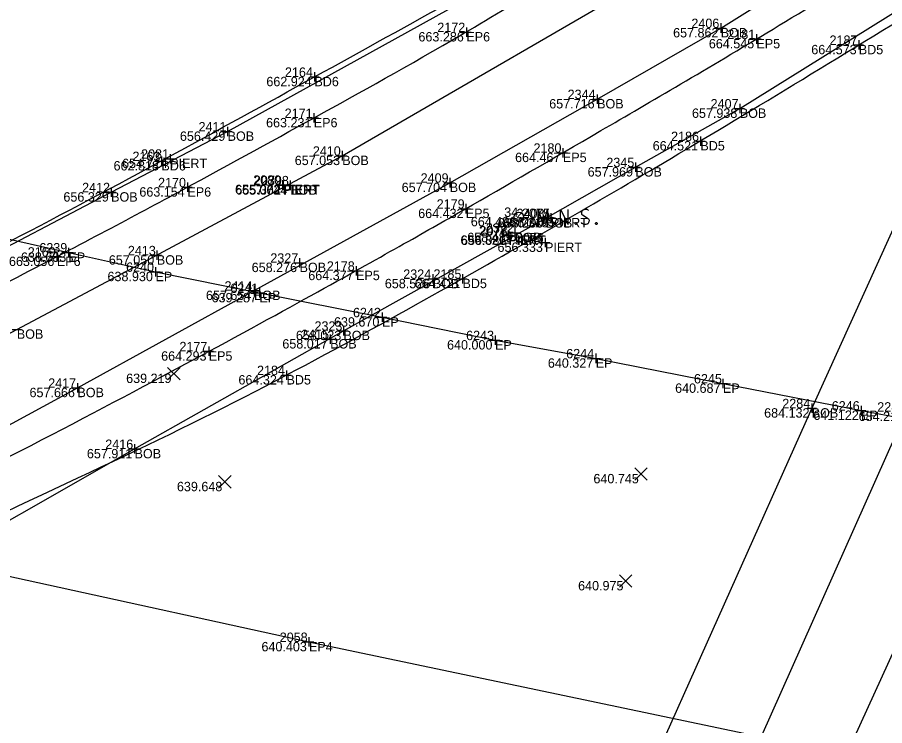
# Model space of a CAD drawing. Extents: x 2197382 to 2204062, y 634117 to 636522.
# Drawn here: x 2202538.2 to 2202630.7, y 635231.8 to 635307.3 of the extents above; entities that cross this region are included whole.
import ezdxf

# ---------------------------------------------------------------- set-up
doc = ezdxf.new("R2010")
doc.units = 0
for name, color, linetype in [('_CIVIL_CONSTRUCTION', 7, 'Continuous'), ('BR_X_SV_Bottom_of_Beam', 7, 'Continuous'), ('BR_X_SV_Bottom_of_Beam_Text', 7, 'Continuous'), ('BR_X_SV_Deck_Top', 7, 'Continuous'), ('BR_X_SV_Deck_Top_Text', 7, 'Continuous'), ('BR_X_SV_Pier_Cap_Top_Text', 7, 'Continuous'), ('GE_P_Alignment_100_Distances', 7, 'Continuous'), ('RW_X_CL_100_Curve_Data', 7, 'Continuous'), ('SH_Border', 7, 'Continuous'), ('SH_Cut_Line', 7, 'Continuous'), ('SH_Data', 7, 'Continuous'), ('SV_P_Control_Cells_Set', 7, 'Continuous')]:
    doc.layers.add(name, color=color, linetype=linetype)

msp = doc.modelspace()

# ---------------------------------------------------------------- linework, layer by layer
at = {"layer": '_CIVIL_CONSTRUCTION'}
for p, q in [((2202586.089, 635306.205), (2202586.089, 635305.205)), ((2202612.695, 635306.135), (2202613.695, 635306.135)), ((2202613.195, 635306.635), (2202613.195, 635305.635)), ((2202613.195, 635306.135), (2202613.195, 635306.135)), ((2202585.589, 635305.705), (2202586.589, 635305.705)), ((2202586.089, 635305.705), (2202586.089, 635305.705)), ((2202617, 635305.468), (2202617, 635304.468)), ((2202616.5, 635304.968), (2202617.5, 635304.968)), ((2202617, 635304.968), (2202617, 635304.968)), ((2202627.41, 635304.339), (2202628.41, 635304.339)), ((2202627.91, 635304.839), (2202627.91, 635303.839)), ((2202627.91, 635304.339), (2202627.91, 635304.339)), ((2202569.901, 635301.433), (2202569.901, 635300.433)), ((2202569.401, 635300.933), (2202570.401, 635300.933)), ((2202569.901, 635300.933), (2202569.901, 635300.933)), ((2202599.525, 635298.569), (2202600.525, 635298.569)), ((2202600.025, 635299.069), (2202600.025, 635298.069)), ((2202600.025, 635298.569), (2202600.025, 635298.569)), ((2202615.232, 635298.065), (2202615.232, 635297.065)), ((2202569.832, 635297.056), (2202569.832, 635296.056)), ((2202614.732, 635297.565), (2202615.732, 635297.565)), ((2202615.232, 635297.565), (2202615.232, 635297.565)), ((2202569.332, 635296.556), (2202570.332, 635296.556)), ((2202569.832, 635296.556), (2202569.832, 635296.556)), ((2202560.151, 635295.117), (2202561.151, 635295.117)), ((2202560.651, 635295.617), (2202560.651, 635294.617)), ((2202560.651, 635295.117), (2202560.651, 635295.117)), ((2202610.53, 635294.094), (2202611.53, 635294.094)), ((2202611.03, 635294.594), (2202611.03, 635293.594)), ((2202611.03, 635294.094), (2202611.03, 635294.094)), ((2202572.867, 635293.036), (2202572.867, 635292.036)), ((2202596.38, 635293.354), (2202596.38, 635292.354)), ((2202553.597, 635292.463), (2202553.597, 635291.463)), ((2202554.029, 635292.215), (2202555.029, 635292.215)), ((2202554.529, 635292.715), (2202554.529, 635291.715)), ((2202554.529, 635292.215), (2202554.529, 635292.215)), ((2202572.367, 635292.536), (2202573.367, 635292.536)), ((2202572.867, 635292.536), (2202572.867, 635292.536)), ((2202595.88, 635292.854), (2202596.88, 635292.854)), ((2202596.38, 635292.854), (2202596.38, 635292.854)), ((2202553.097, 635291.963), (2202554.097, 635291.963)), ((2202553.597, 635291.963), (2202553.597, 635291.963)), ((2202603.599, 635291.315), (2202604.599, 635291.315)), ((2202604.099, 635291.815), (2202604.099, 635290.815)), ((2202604.099, 635291.315), (2202604.099, 635291.315)), ((2202556.369, 635289.676), (2202556.369, 635288.676)), ((2202566.011, 635289.444), (2202567.011, 635289.444)), ((2202566.058, 635289.393), (2202567.058, 635289.393)), ((2202566.511, 635289.944), (2202566.511, 635288.944)), ((2202566.511, 635289.444), (2202566.511, 635289.444)), ((2202566.558, 635289.893), (2202566.558, 635288.893)), ((2202566.558, 635289.393), (2202566.558, 635289.393)), ((2202566.822, 635289.379), (2202567.822, 635289.379)), ((2202567.322, 635289.879), (2202567.322, 635288.879)), ((2202567.322, 635289.379), (2202567.322, 635289.379)), ((2202583.822, 635289.661), (2202584.822, 635289.661)), ((2202584.322, 635290.161), (2202584.322, 635289.161)), ((2202584.322, 635289.661), (2202584.322, 635289.661)), ((2202547.737, 635288.645), (2202548.737, 635288.645)), ((2202548.237, 635289.145), (2202548.237, 635288.145)), ((2202548.237, 635288.645), (2202548.237, 635288.645)), ((2202555.869, 635289.176), (2202556.869, 635289.176)), ((2202556.369, 635289.176), (2202556.369, 635289.176)), ((2202585.532, 635286.892), (2202586.532, 635286.892)), ((2202586.032, 635287.392), (2202586.032, 635286.392)), ((2202586.032, 635286.892), (2202586.032, 635286.892)), ((2202594.056, 635285.879), (2202595.056, 635285.879)), ((2202594.556, 635286.379), (2202594.556, 635285.379)), ((2202594.556, 635285.879), (2202594.556, 635285.879)), ((2202594.606, 635285.901), (2202595.606, 635285.901)), ((2202595.106, 635286.401), (2202595.106, 635285.401)), ((2202595.106, 635285.901), (2202595.106, 635285.901)), ((2202591.265, 635284.831), (2202591.265, 635283.831)), ((2202590.044, 635284.055), (2202591.044, 635284.055)), ((2202590.118, 635284.025), (2202591.118, 635284.025)), ((2202590.544, 635284.555), (2202590.544, 635283.555)), ((2202590.544, 635284.055), (2202590.544, 635284.055)), ((2202590.618, 635284.525), (2202590.618, 635283.525)), ((2202590.618, 635284.025), (2202590.618, 635284.025)), ((2202590.765, 635284.331), (2202591.765, 635284.331)), ((2202591.265, 635284.331), (2202591.265, 635284.331)), ((2202594.475, 635283.789), (2202594.475, 635282.789)), ((2202593.975, 635283.289), (2202594.975, 635283.289)), ((2202594.475, 635283.289), (2202594.475, 635283.289)), ((2202542.454, 635282.285), (2202542.454, 635281.285)), ((2202543.188, 635282.23), (2202544.188, 635282.23)), ((2202543.688, 635282.73), (2202543.688, 635281.73)), ((2202543.688, 635282.23), (2202543.688, 635282.23)), ((2202552.607, 635281.931), (2202553.607, 635281.931)), ((2202553.107, 635282.431), (2202553.107, 635281.431)), ((2202553.107, 635281.931), (2202553.107, 635281.931)), ((2202541.954, 635281.785), (2202542.954, 635281.785)), ((2202542.454, 635281.785), (2202542.454, 635281.785)), ((2202567.819, 635281.138), (2202568.819, 635281.138)), ((2202568.319, 635281.638), (2202568.319, 635280.638)), ((2202568.319, 635281.138), (2202568.319, 635281.138)), ((2202552.465, 635280.17), (2202553.465, 635280.17)), ((2202552.965, 635280.67), (2202552.965, 635279.67)), ((2202552.965, 635280.17), (2202552.965, 635280.17)), ((2202573.84, 635280.28), (2202574.84, 635280.28)), ((2202574.34, 635280.78), (2202574.34, 635279.78)), ((2202574.34, 635280.28), (2202574.34, 635280.28)), ((2202582.008, 635279.418), (2202583.008, 635279.418)), ((2202582.508, 635279.918), (2202582.508, 635278.918)), ((2202582.508, 635279.418), (2202582.508, 635279.418)), ((2202585.177, 635279.428), (2202586.177, 635279.428)), ((2202585.677, 635279.928), (2202585.677, 635278.928)), ((2202585.677, 635279.428), (2202585.677, 635279.428)), ((2202563.463, 635278.661), (2202563.463, 635277.661)), ((2202564.038, 635278.417), (2202564.038, 635277.417)), ((2202562.963, 635278.161), (2202563.963, 635278.161)), ((2202563.463, 635278.161), (2202563.463, 635278.161)), ((2202563.538, 635277.917), (2202564.538, 635277.917)), ((2202564.038, 635277.917), (2202564.038, 635277.917)), ((2202577.102, 635275.828), (2202577.102, 635274.828)), ((2202576.602, 635275.328), (2202577.602, 635275.328)), ((2202577.102, 635275.328), (2202577.102, 635275.328)), ((2202537.689, 635274.036), (2202538.689, 635274.036)), ((2202572.492, 635273.891), (2202573.492, 635273.891)), ((2202572.992, 635274.391), (2202572.992, 635273.391)), ((2202572.992, 635273.891), (2202572.992, 635273.891)), ((2202571.077, 635272.998), (2202572.077, 635272.998)), ((2202571.577, 635273.498), (2202571.577, 635272.498)), ((2202571.577, 635272.998), (2202571.577, 635272.998)), ((2202588.648, 635272.888), (2202589.648, 635272.888)), ((2202589.148, 635273.388), (2202589.148, 635272.388)), ((2202589.148, 635272.888), (2202589.148, 635272.888)), ((2202558.633, 635272.203), (2202558.633, 635271.203)), ((2202558.133, 635271.703), (2202559.133, 635271.703)), ((2202558.633, 635271.703), (2202558.633, 635271.703)), ((2202599.374, 635270.951), (2202600.374, 635270.951)), ((2202599.874, 635271.451), (2202599.874, 635270.451)), ((2202599.874, 635270.951), (2202599.874, 635270.951)), ((2202566.427, 635269.164), (2202567.427, 635269.164)), ((2202566.927, 635269.664), (2202566.927, 635268.664)), ((2202566.927, 635269.164), (2202566.927, 635269.164)), ((2202544.646, 635268.314), (2202544.646, 635267.314)), ((2202612.935, 635268.276), (2202613.935, 635268.276)), ((2202613.435, 635268.776), (2202613.435, 635267.776)), ((2202613.435, 635268.276), (2202613.435, 635268.276)), ((2202544.146, 635267.814), (2202545.146, 635267.814)), ((2202544.646, 635267.814), (2202544.646, 635267.814)), ((2202622.397, 635265.637), (2202623.397, 635265.637)), ((2202622.897, 635266.137), (2202622.897, 635265.137)), ((2202622.897, 635265.637), (2202622.897, 635265.637)), ((2202627.65, 635265.389), (2202628.65, 635265.389)), ((2202628.15, 635265.889), (2202628.15, 635264.889)), ((2202628.15, 635265.389), (2202628.15, 635265.389)), ((2202550.738, 635261.8), (2202550.738, 635260.8)), ((2202550.238, 635261.3), (2202551.238, 635261.3)), ((2202550.738, 635261.3), (2202550.738, 635261.3)), ((2202569.322, 635241.242), (2202569.322, 635240.242)), ((2202568.822, 635240.742), (2202569.822, 635240.742)), ((2202569.322, 635240.742), (2202569.322, 635240.742))]:
    msp.add_line(p, q, dxfattribs=at)
at = {"layer": 'BR_X_SV_Bottom_of_Beam'}
for points in [[(2202550.738, 635261.3), (2202572.992, 635273.891), (2202594.556, 635285.879), (2202604.099, 635291.315), (2202615.232, 635297.565), (2202632.636, 635308.407), (2202649.916, 635319.32), (2202686.545, 635342.9), (2202715.55, 635365.054), (2202734.551, 635379.543), (2202765.2, 635403.192), (2202782.887, 635418.269), (2202797.351, 635430.625), (2202810.639, 635442.162), (2202822.488, 635452.15)], [(2202513.324, 635270.745), (2202518.461, 635273.222), (2202532.26, 635280.283), (2202548.237, 635288.645), (2202560.651, 635295.117), (2202588.283, 635310.399), (2202608.693, 635322.992), (2202620.515, 635330.213), (2202626.072, 635333.707), (2202636.254, 635340.133), (2202656.933, 635353.888), (2202662.455, 635358.969), (2202720.902, 635399.769), (2202735.154, 635410.438), (2202760.7, 635432.077)], [(2202698.738, 635432.336), (2202647.005, 635318.77), (2202622.897, 635265.637), (2202604.224, 635223.888), (2202566.194, 635137.247)], [(2202700.297, 635413.559), (2202652.906, 635308.886), (2202632.96, 635265.277), (2202616.353, 635228.13), (2202571.256, 635128.111)], [(2202692.588, 635374.159), (2202661.746, 635305.712), (2202642.152, 635262.855), (2202627.428, 635230.558), (2202583.755, 635133.025)], [(2202600.025, 635298.569), (2202613.195, 635306.135), (2202629.349, 635316.236), (2202645.46, 635326.182), (2202658.228, 635335.017), (2202675.533, 635345.812), (2202692.151, 635358.452)], [(2202572.867, 635292.536), (2202609.773, 635313.94), (2202624.848, 635323.108)], [(2202480.61, 635236.776), (2202503.22, 635246.466), (2202521.809, 635255.415), (2202544.646, 635267.814), (2202563.463, 635278.161), (2202584.322, 635289.661), (2202600.025, 635298.569)], [(2202469.79, 635240.642), (2202482.107, 635245.978), (2202495.671, 635251.668), (2202517.657, 635263.17), (2202538.189, 635274.036), (2202552.84, 635281.789), (2202572.867, 635292.536)], [(2202495.198, 635233.737), (2202513.073, 635241.549), (2202526.429, 635247.455), (2202550.738, 635261.3)]]:
    msp.add_lwpolyline(points, dxfattribs=at)
at = {"layer": 'BR_X_SV_Deck_Top'}
for points in [[(2202430.051, 635233.588), (2202439.74, 635238.507), (2202466.339, 635247.691), (2202507.168, 635268.028), (2202543.723, 635286.397), (2202574.877, 635303.715), (2202604.911, 635320.157), (2202634.127, 635339.4), (2202663.018, 635358.594), (2202692.445, 635376.507), (2202729.246, 635404.451), (2202755.806, 635426.417), (2202769.739, 635438.84)], [(2202458.051, 635216.681), (2202477.116, 635219.979), (2202511.723, 635243.78), (2202554.955, 635262.299), (2202588.014, 635280.674), (2202608.342, 635292.387), (2202640.833, 635312.137), (2202668.147, 635329.948), (2202698.573, 635351.315), (2202722.135, 635368.649), (2202754.604, 635393.426), (2202777.494, 635412.293), (2202789.607, 635422.635)], [(2202895.365, 635391.811), (2202885.347, 635387.334), (2202865.192, 635377.205), (2202839.037, 635363.762), (2202813.103, 635349.723), (2202789.18, 635336.138), (2202762.388, 635320.287), (2202740.668, 635306.565), (2202716.628, 635290.831), (2202693.394, 635275.343), (2202664.567, 635254.787), (2202633.536, 635231.765), (2202595.89, 635201.643), (2202569.397, 635178.622), (2202555.165, 635165.675)], [(2202923.181, 635376.197), (2202906.167, 635369.085), (2202881.487, 635355.934), (2202846.739, 635338.13), (2202819.013, 635322.649), (2202790.142, 635306.09), (2202754.022, 635283.778), (2202709.422, 635255.583), (2202663.285, 635220.884), (2202620.566, 635187.914), (2202595.285, 635167.396), (2202582.509, 635156.81)]]:
    msp.add_open_spline(points, degree=3, dxfattribs=at)
at = {"layer": 'GE_P_Alignment_100_Distances'}
for points in [[(2202498.738, 635292.198), (2202504.316, 635290.969), (2202510.464, 635289.53), (2202518.118, 635287.829), (2202527.68, 635285.66), (2202535.473, 635284.068), (2202543.688, 635282.23), (2202552.965, 635280.17), (2202564.038, 635277.917), (2202577.102, 635275.328), (2202589.148, 635272.888), (2202599.874, 635270.951), (2202613.435, 635268.276), (2202628.15, 635265.389), (2202641.924, 635262.824), (2202654.395, 635260.657), (2202664.333, 635258.843), (2202676.156, 635256.722), (2202690.385, 635253.856), (2202704.424, 635251.17), (2202718.674, 635248.712), (2202737.349, 635245.359), (2202761.228, 635240.853), (2202781.345, 635237.182)], [(2202482.631, 635259.703), (2202569.322, 635240.742), (2202617.178, 635230.71), (2202631.863, 635227.588), (2202654.833, 635223.139), (2202694.019, 635215.687), (2202726.451, 635210.27), (2202846.078, 635190.299)]]:
    msp.add_lwpolyline(points, dxfattribs=at)
for points in [[(2202483.163, 635252.761), (2202495.402, 635258.227), (2202515.209, 635267.824), (2202539.505, 635280.183), (2202556.272, 635289.074), (2202570.794, 635297.089), (2202585.76, 635305.335), (2202607.83, 635319.01), (2202630.778, 635332.646), (2202656.431, 635348.815), (2202675.69, 635362.468), (2202698.981, 635379.185), (2202729.904, 635401.353), (2202753.674, 635420.874), (2202767.823, 635433.185)], [(2202457.668, 635223.282), (2202466.48, 635226.872), (2202500.455, 635242.355), (2202539.476, 635261.183), (2202573.06, 635279.52), (2202585.609, 635286.631), (2202599.84, 635294.842), (2202617.618, 635305.231), (2202642.294, 635320.395), (2202667.372, 635336.77), (2202691.723, 635353.633), (2202713.413, 635369.403), (2202739.641, 635388.973), (2202758.657, 635404.276), (2202770.061, 635413.813)], [(2202926.993, 635398.223), (2202911.054, 635391.267), (2202884.78, 635379.221), (2202850.251, 635362.173), (2202828.215, 635350.038), (2202808.09, 635339.198), (2202790.855, 635329.045), (2202764, 635313.325), (2202738.781, 635297.635), (2202713.051, 635280.577), (2202697.019, 635269.602), (2202684.529, 635260.864), (2202668.986, 635249.754), (2202642.65, 635230.806), (2202596.561, 635193.887), (2202560.681, 635163.156), (2202538.312, 635142.813)], [(2202919.499, 635378.368), (2202901.447, 635370.678), (2202875.936, 635356.879), (2202844.592, 635341.598), (2202825.856, 635330.823), (2202809.466, 635322.019), (2202780.051, 635304.409), (2202746.062, 635282.999), (2202707.717, 635258.176), (2202682.244, 635240.209), (2202658.947, 635222.257), (2202614.143, 635189.251), (2202577.354, 635157.516), (2202549.508, 635131.427)]]:
    msp.add_open_spline(points, degree=3, dxfattribs=at)
at = {"layer": 'RW_X_CL_100_Curve_Data'}
for p, q in [((2202554.256, 635268.654), (2202555.59, 635269.99)), ((2202554.256, 635269.99), (2202555.59, 635268.654)), ((2202604.036, 635257.97), (2202605.37, 635259.304)), ((2202604.036, 635259.304), (2202605.37, 635257.97)), ((2202559.682, 635257.127), (2202561.016, 635258.463)), ((2202559.682, 635258.463), (2202561.016, 635257.127)), ((2202602.401, 635246.566), (2202603.735, 635247.902)), ((2202602.401, 635247.902), (2202603.735, 635246.566))]:
    msp.add_line(p, q, dxfattribs=at)
at = {"layer": 'SV_P_Control_Cells_Set'}
for points in [[(2202593.76, 635285.215), (2202593.76, 635286.815), (2202594.267, 635285.215), (2202594.752, 635286.815), (2202594.752, 635285.215)], [(2202596.13, 635285.215), (2202596.13, 635286.815), (2202596.957, 635285.215), (2202596.957, 635286.815)], [(2202599.107, 635286.702), (2202599.085, 635286.727), (2202599.051, 635286.752), (2202598.952, 635286.79), (2202598.831, 635286.815), (2202598.743, 635286.815), (2202598.71, 635286.815), (2202598.566, 635286.778), (2202598.445, 635286.702), (2202598.368, 635286.601), (2202598.346, 635286.5), (2202598.346, 635286.425), (2202598.368, 635286.324), (2202598.456, 635286.236), (2202599.063, 635285.858), (2202599.118, 635285.808), (2202599.14, 635285.757), (2202599.162, 635285.682), (2202599.162, 635285.606), (2202599.151, 635285.53), (2202599.14, 635285.48), (2202599.118, 635285.417), (2202599.096, 635285.367), (2202599.073, 635285.329), (2202599.04, 635285.291), (2202599.007, 635285.266), (2202598.963, 635285.241), (2202598.93, 635285.228), (2202598.831, 635285.215), (2202598.677, 635285.215), (2202598.578, 635285.241), (2202598.434, 635285.329), (2202598.346, 635285.404)], [(2202595.524, 635285.43), (2202595.579, 635285.43), (2202595.612, 635285.404), (2202595.645, 635285.354), (2202595.645, 635285.291), (2202595.612, 635285.241), (2202595.579, 635285.215), (2202595.524, 635285.215), (2202595.491, 635285.241), (2202595.458, 635285.291), (2202595.458, 635285.354), (2202595.491, 635285.404), (2202595.524, 635285.43)], [(2202597.74, 635285.43), (2202597.795, 635285.43), (2202597.828, 635285.404), (2202597.861, 635285.354), (2202597.861, 635285.291), (2202597.828, 635285.241), (2202597.795, 635285.215), (2202597.74, 635285.215), (2202597.707, 635285.241), (2202597.674, 635285.291), (2202597.674, 635285.354), (2202597.707, 635285.404), (2202597.74, 635285.43)], [(2202599.922, 635285.43), (2202599.977, 635285.43), (2202600.011, 635285.404), (2202600.043, 635285.354), (2202600.043, 635285.291), (2202600.011, 635285.241), (2202599.977, 635285.215), (2202599.922, 635285.215), (2202599.889, 635285.241), (2202599.856, 635285.291), (2202599.856, 635285.354), (2202599.889, 635285.404), (2202599.922, 635285.43)]]:
    msp.add_lwpolyline(points, dxfattribs=at)
msp.add_circle((2202591.671, 635286.015), 0.497, dxfattribs=at)

# ---------------------------------------------------------------- texts
at = {"layer": 'BR_X_SV_Bottom_of_Beam_Text'}
for s, p in [('2406', (2202610.072, 635306.135)), ('657.862', (2202608.122, 635305.135)), ('BOB', (2202613.195, 635305.135)), ('2344', (2202596.884, 635298.569)), ('657.716', (2202594.921, 635297.569)), ('BOB', (2202600.025, 635297.569)), ('2407', (2202612.117, 635297.565)), ('657.938', (2202610.132, 635296.565)), ('BOB', (2202615.232, 635296.565)), ('2411', (2202557.551, 635295.117)), ('656.429', (2202555.567, 635294.117)), ('BOB', (2202560.651, 635294.117)), ('2410', (2202569.735, 635292.536)), ('657.053', (2202567.803, 635291.536)), ('BOB', (2202572.867, 635291.536)), ('2345', (2202601.01, 635291.315)), ('657.969', (2202599.015, 635290.315)), ('BOB', (2202604.099, 635290.315)), ('2328', (2202564.203, 635289.379)), ('2409', (2202581.22, 635289.661)), ('2412', (2202545.145, 635288.645)), ('657.044', (2202562.2, 635288.379)), ('BOB', (2202567.322, 635288.379)), ('657.704', (2202579.2, 635288.661)), ('BOB', (2202584.322, 635288.661)), ('656.329', (2202543.153, 635287.645)), ('BOB', (2202548.237, 635287.645)), ('2408', (2202591.437, 635285.879)), ('658.200', (2202589.442, 635284.879)), ('BOB', (2202594.556, 635284.879)), ('2322', (2202588.173, 635284.331)), ('658.489', (2202586.181, 635283.331)), ('BOB', (2202591.265, 635283.331)), ('2413', (2202550.024, 635281.931)), ('657.050', (2202547.993, 635280.931)), ('BOB', (2202553.107, 635280.931)), ('2327', (2202565.204, 635281.138)), ('658.276', (2202563.215, 635280.138)), ('BOB', (2202568.319, 635280.138)), ('2324', (2202579.367, 635279.418)), ('2414', (2202560.322, 635278.161)), ('658.526', (2202577.404, 635278.418)), ('BOB', (2202582.508, 635278.418)), ('657.654', (2202558.341, 635277.161)), ('BOB', (2202563.463, 635277.161)), ('2323', (2202569.909, 635273.891)), ('BOB', (2202538.189, 635273.036)), ('658.023', (2202567.928, 635272.891)), ('2415', (2202568.488, 635272.998)), ('BOB', (2202572.992, 635272.891)), ('658.017', (2202566.481, 635271.998)), ('BOB', (2202571.577, 635271.998)), ('2417', (2202541.531, 635267.814)), ('657.666', (2202539.542, 635266.814)), ('BOB', (2202544.646, 635266.814)), ('2284', (2202619.756, 635265.637)), ('2283', (2202629.877, 635265.277)), ('684.132', (2202617.824, 635264.637)), ('BOB', (2202622.897, 635264.637)), ('684.213', (2202627.896, 635264.277)), ('2416', (2202547.615, 635261.3)), ('657.911', (2202545.656, 635260.3)), ('BOB', (2202550.738, 635260.3))]:
    msp.add_text(s, height=1, dxfattribs=at).set_placement(p)
at = {"layer": 'BR_X_SV_Deck_Top_Text'}
for s, p in [('2187', (2202624.795, 635304.339)), ('664.573', (2202622.846, 635303.339)), ('BD5', (2202627.91, 635303.339)), ('2164', (2202566.76, 635300.933)), ('662.924', (2202564.779, 635299.933)), ('BD6', (2202569.901, 635299.933)), ('2186', (2202607.907, 635294.094)), ('664.521', (2202605.948, 635293.094)), ('BD5', (2202611.03, 635293.094)), ('2163', (2202550.514, 635291.963)), ('662.818', (2202548.497, 635290.963)), ('BD6', (2202553.597, 635290.963)), ('2185', (2202582.588, 635279.428)), ('664.421', (2202580.595, 635278.428)), ('BD5', (2202585.677, 635278.428)), ('2184', (2202563.786, 635269.164)), ('664.324', (2202561.805, 635268.164)), ('BD5', (2202566.927, 635268.164))]:
    msp.add_text(s, height=1, dxfattribs=at).set_placement(p)
at = {"layer": 'BR_X_SV_Pier_Cap_Top_Text'}
for s, p in [('2081', (2202551.429, 635292.215)), ('654.714', (2202549.407, 635291.215)), ('PIERT', (2202554.529, 635291.215)), ('2080', (2202563.379, 635289.444)), ('2079', (2202563.456, 635289.393)), ('655.072', (2202561.438, 635288.444)), ('655.362', (2202561.485, 635288.393)), ('PIERT', (2202566.511, 635288.444)), ('PIERT', (2202566.558, 635288.393)), ('2075', (2202592.017, 635285.901)), ('656.319', (2202590.022, 635284.901)), ('PIERT', (2202595.106, 635284.901)), ('2077', (2202587.429, 635284.055)), ('2078', (2202587.499, 635284.025)), ('656.321', (2202585.462, 635283.055)), ('656.086', (2202585.514, 635283.025)), ('PIERT', (2202590.544, 635283.055)), ('PIERT', (2202590.618, 635283.025)), ('2076', (2202591.352, 635283.289)), ('656.333', (2202589.411, 635282.289)), ('PIERT', (2202594.475, 635282.289))]:
    msp.add_text(s, height=1, dxfattribs=at).set_placement(p)
at = {"layer": 'SH_Border'}
for s, p in [('EP6', (2202586.089, 635304.705)), ('EP5', (2202617, 635303.968)), ('EP6', (2202569.832, 635295.556)), ('EP5', (2202596.38, 635291.854)), ('EP6', (2202556.369, 635288.176)), ('EP5', (2202586.032, 635285.892)), ('MAGS', (2202591.67, 635285.016)), ('EP', (2202543.688, 635281.23)), ('EP6', (2202542.454, 635280.785)), ('EP', (2202552.965, 635279.17)), ('EP5', (2202574.34, 635279.28)), ('EP', (2202564.038, 635276.917)), ('EP', (2202577.102, 635274.328)), ('EP', (2202589.148, 635271.888)), ('EP5', (2202558.633, 635270.703)), ('EP', (2202599.874, 635269.951)), ('EP', (2202613.435, 635267.276)), ('EP', (2202628.15, 635264.389)), ('EP4', (2202569.322, 635239.742))]:
    msp.add_text(s, height=1, dxfattribs=at).set_placement(p)
at = {"layer": 'SH_Cut_Line'}
for s, p in [('2172', (2202582.997, 635305.705)), ('2181', (2202613.9, 635304.968)), ('2171', (2202566.732, 635296.556)), ('2180', (2202593.248, 635292.854)), ('2170', (2202553.237, 635289.176)), ('2179', (2202582.93, 635286.892)), ('34', (2202590.125, 635286.016)), ('6239', (2202540.586, 635282.23)), ('2169', (2202539.352, 635281.785)), ('6240', (2202549.833, 635280.17)), ('2178', (2202571.221, 635280.28)), ('6241', (2202560.938, 635277.917)), ('6242', (2202574.01, 635275.328)), ('6243', (2202586.065, 635272.888)), ('2177', (2202555.518, 635271.703)), ('6244', (2202596.733, 635270.951)), ('6245', (2202610.346, 635268.276)), ('6246', (2202625.027, 635265.389)), ('2058', (2202566.203, 635240.742))]:
    msp.add_text(s, height=1, dxfattribs=at).set_placement(p)
at = {"layer": 'SH_Data'}
for s, p in [('663.286', (2202580.985, 635304.705)), ('664.545', (2202611.93, 635303.968)), ('663.231', (2202564.75, 635295.556)), ('664.467', (2202591.284, 635291.854)), ('663.154', (2202551.247, 635288.176)), ('664.432', (2202580.959, 635285.892)), ('664.496', (2202586.566, 635285.016)), ('638.633', (2202538.624, 635281.23)), ('663.056', (2202537.35, 635280.785)), ('638.930', (2202547.851, 635279.17)), ('664.377', (2202569.244, 635279.28)), ('639.287', (2202558.942, 635276.917)), ('639.670', (2202571.988, 635274.328)), ('640.000', (2202584.034, 635271.888)), ('664.293', (2202553.569, 635270.703)), ('640.327', (2202594.778, 635269.951)), ('639.219', (2202549.839, 635268.322)), ('640.687', (2202608.339, 635267.276)), ('641.122', (2202623.077, 635264.389)), ('640.745', (2202599.633, 635257.637)), ('639.648', (2202555.249, 635256.795)), ('640.975', (2202597.998, 635246.234)), ('640.403', (2202564.258, 635239.742))]:
    msp.add_text(s, height=1, dxfattribs=at).set_placement(p)

doc.saveas('drawing.dxf')
